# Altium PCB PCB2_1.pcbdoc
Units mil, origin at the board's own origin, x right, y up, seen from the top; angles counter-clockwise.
Board outline 3056.28 x 1755 mil, 2 copper layers (Top Layer, Bottom Layer); 62 components, 47 nets, 218 pads, 29 vias.
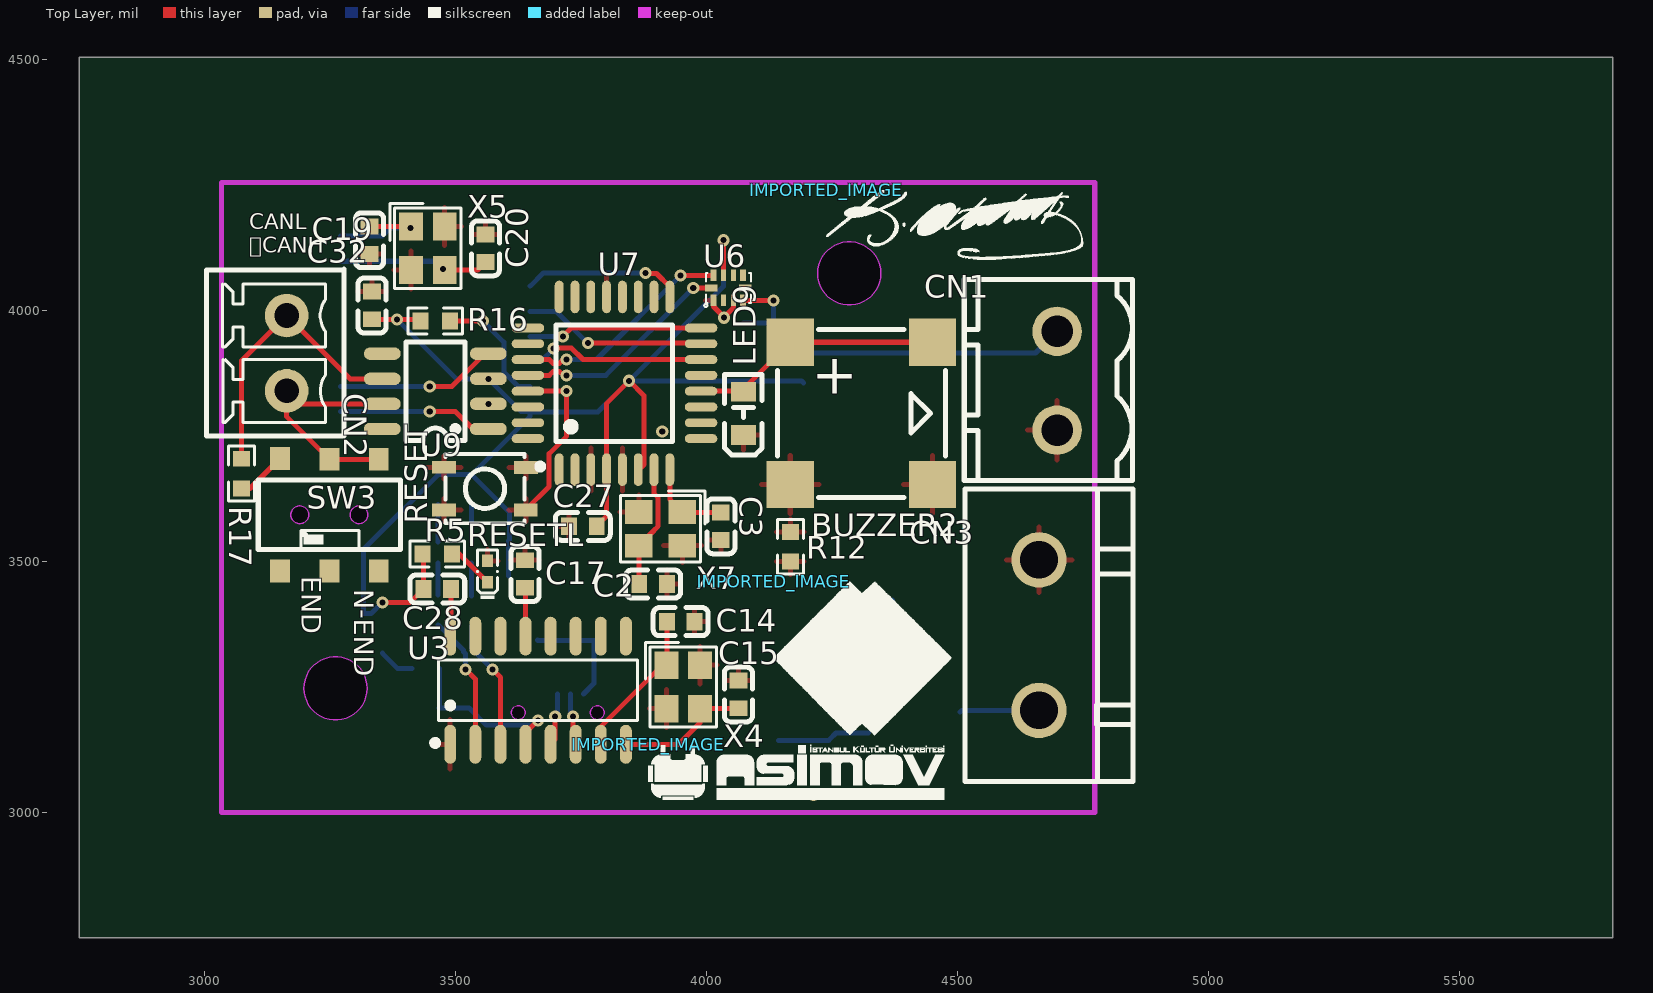
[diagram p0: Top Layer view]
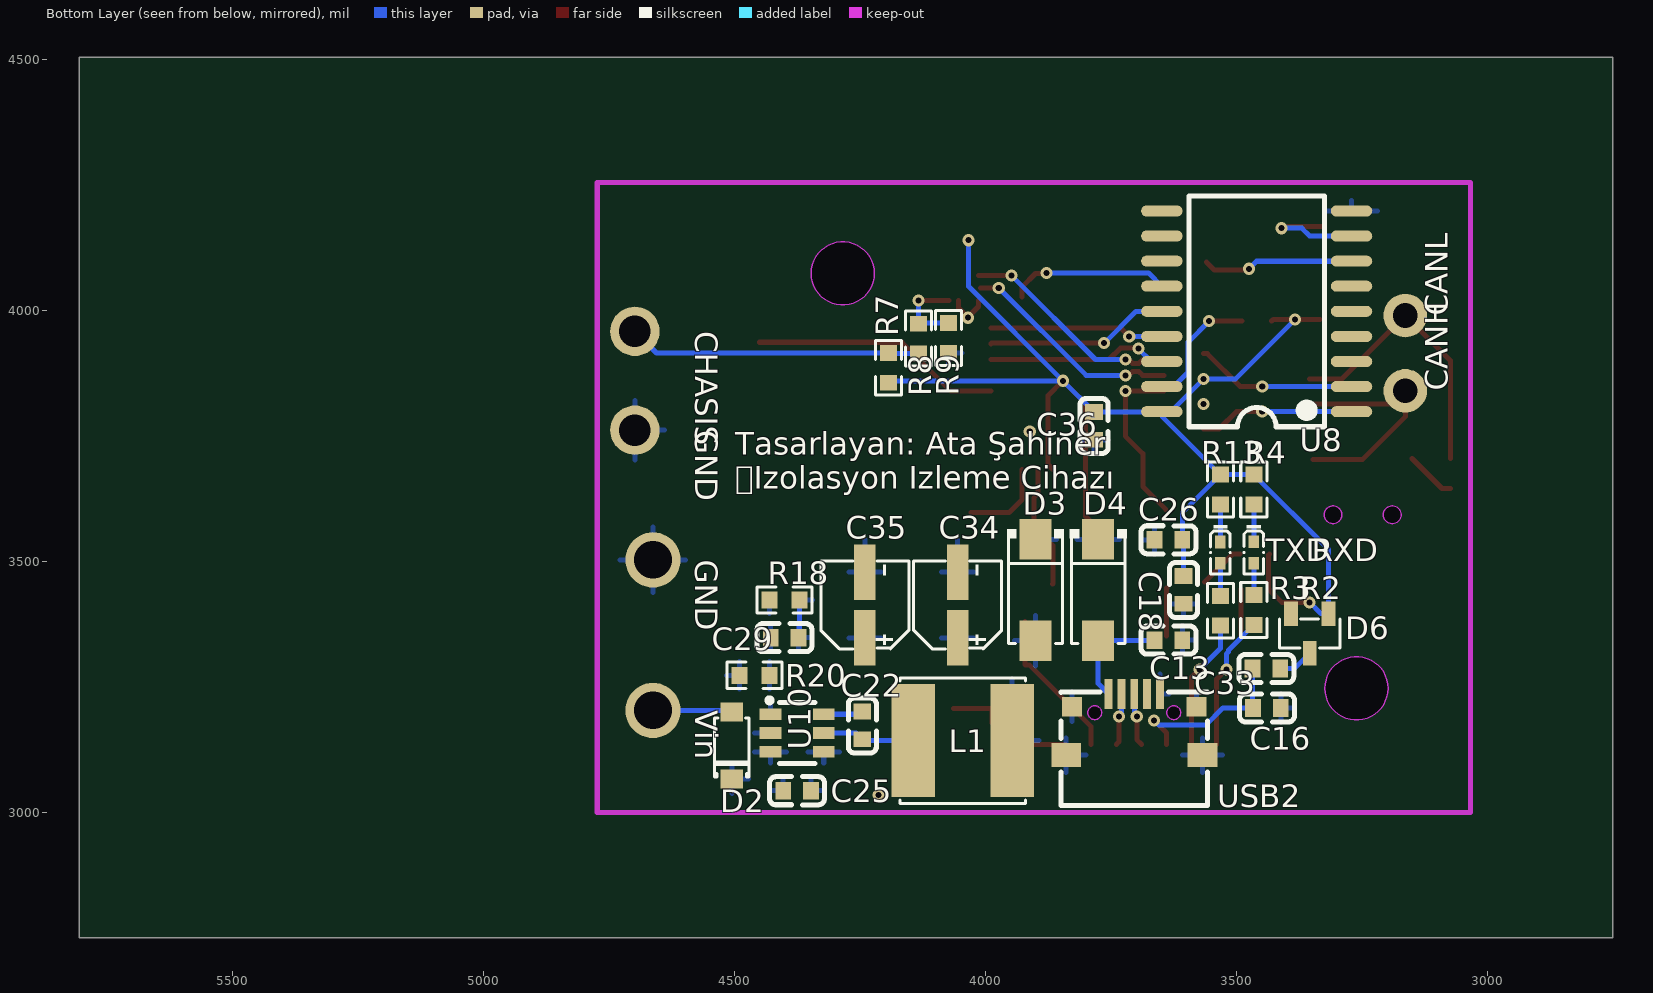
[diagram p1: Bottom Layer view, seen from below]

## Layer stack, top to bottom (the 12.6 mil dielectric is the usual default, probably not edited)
Top Layer: signal copper (thickness not stored)
Dielectric: dielectric 12.6, FR-4, Dk 4.8
Bottom Layer: signal copper (thickness not stored)

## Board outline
5806.28,2750 2750,2750 2750,4505 5806.28,4505
cut-out: 3323.98,3247.13 cw(c3260.99,3247.13) 3197.99,3247.13 cw(c3260.99,3247.13)
cut-out: 4347.6,4073.9 cw(c4284.61,4073.9) 4221.62,4073.9 cw(c4284.61,4073.9)

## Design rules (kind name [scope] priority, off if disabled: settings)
BoardOutlineClearance copperThickness1oz [All] p0: genericclearance=10 ignorepadtopadclearanceinfootprint=FALSE except(0: Arc-SplitContinuation Track-SplitContinuation SMDPad-SplitContinuation THPad-SplitContinuation Via-SplitContinuation Fill-SplitContinuation Poly-SplitContinuation Region-SplitContinuation Text-SplitContinuation; 6: Track-CutoutEdge SMDPad-CutoutEdge THPad-CutoutEdge Via-CutoutEdge Region-CutoutEdge; 11.8: Track-OutlineEdge SMDPad-OutlineEdge THPad-OutlineEdge Via-OutlineEdge Fill-OutlineEdge Region-OutlineEdge Poly-OutlineEdge Text-OutlineEdge Fill-CutoutEdge)
BoardOutlineClearance copperThickness2oz [All] p0: genericclearance=10 ignorepadtopadclearanceinfootprint=FALSE except(0: Arc-SplitContinuation Track-SplitContinuation SMDPad-SplitContinuation THPad-SplitContinuation Via-SplitContinuation Fill-SplitContinuation Poly-SplitContinuation Region-SplitContinuation Text-SplitContinuation; 6: Track-CutoutEdge SMDPad-CutoutEdge THPad-CutoutEdge Via-CutoutEdge Region-CutoutEdge; 11.8: Track-OutlineEdge SMDPad-OutlineEdge THPad-OutlineEdge Via-OutlineEdge Fill-OutlineEdge Region-OutlineEdge Poly-OutlineEdge Text-OutlineEdge Fill-CutoutEdge)
Clearance copperThickness1oz [(InNet('WARN') OR InNet('$1N38891') OR InNet('GND') OR InNet('XTAL2') OR InNet('$1N1971') OR InNet('XO') OR InNet('$1N3263') OR InNet('$1N3302') OR InNet('RESET') OR InNet('+5V') OR InNet('$1N37305') OR InNet('$1N27741') OR InNet('$1N42220') OR InNet('$1N28334') OR InNet('$1N30372') OR InNet('$1N32397') OR InNet('$1N42230') OR InNet('$1N42278') OR InNet('$1N45861') OR InNet('$1N5233') OR InNet('$1N28331') OR InNet('SDA') OR InNet('SCL') OR InNet('$1N3088') OR InNet('TXD') OR InNet('$1N3089') OR InNet('RXD') OR InNet('$1N44197') OR InNet('TXDC') OR InNet('RXDC') OR InNet('AIN0') OR InNet('$1N13750') OR InNet('$1N2618') OR InNet('INT') OR InNet('SCK') OR InNet('SO') OR InNet('SI') OR InNet('CS') OR InNet('RXCAN') OR InNet('XTAL1') OR InNet('XI') OR InNet('$1N37233') OR InNet('$1N2610') OR InNet('TXCAN') OR InNet('CANL') OR InNet('CANH') OR InNet('$1N53272'))] p1: gap=7 ignorepadtopadclearanceinfootprint=FALSE except(4: Track-Track; 6: Track-SMDPad SMDPad-SMDPad Track-THPad SMDPad-THPad THPad-THPad Track-Via SMDPad-Via THPad-Via Via-Via SMDPad-Fill THPad-Fill Via-Fill Fill-Fill Track-Region SMDPad-Region THPad-Region Via-Region Region-Region Track-Poly SMDPad-Poly THPad-Poly Via-Poly Fill-Poly Region-Poly Poly-Poly Track-Text SMDPad-Text THPad-Text Via-Text Fill-Text Region-Text Poly-Text Text-Text; 6.9: Track-Hole SMDPad-Hole THPad-Hole Via-Hole Fill-Hole Region-Hole Poly-Hole Text-Hole Sheet-Hole; 11.8: Track-Fill Fill-Region Track-Sheet SMDPad-Sheet THPad-Sheet Via-Sheet Fill-Sheet Region-Sheet Poly-Sheet Text-Sheet)
Clearance copperThickness2oz [All] p1: gap=7 ignorepadtopadclearanceinfootprint=FALSE except(6: Track-SMDPad SMDPad-SMDPad Track-THPad SMDPad-THPad THPad-THPad Track-Via SMDPad-Via THPad-Via Via-Via SMDPad-Fill THPad-Fill Via-Fill Fill-Fill Track-Region SMDPad-Region THPad-Region Via-Region Region-Region Track-Poly SMDPad-Poly THPad-Poly Via-Poly Fill-Poly Region-Poly Poly-Poly Track-Text SMDPad-Text THPad-Text Via-Text Fill-Text Region-Text Poly-Text Text-Text; 6.9: Track-Hole SMDPad-Hole THPad-Hole Via-Hole Fill-Hole Region-Hole Poly-Hole Text-Hole Sheet-Hole; 8: Track-Track; 11.8: Track-Fill Fill-Region Track-Sheet SMDPad-Sheet THPad-Sheet Via-Sheet Fill-Sheet Region-Sheet Poly-Sheet Text-Sheet)
DiffPairsRouting differentialPair [All] p1: maxuncoupledlength=10 minlimit=6 maxlimit=6 mostfreqgap=6 toplayer_minwidth=5 toplayer_prefwidth=10 toplayer_maxwidth=100 bottomlayer_minwidth=5 bottomlayer_prefwidth=10 bottomlayer_maxwidth=100
PasteMaskExpansion pasteMaskExpansion [All] p1: expansion=0
PlaneConnect innerPlane [All] p1: planeconnectstyle=Relief reliefexpansion=20 reliefentries=4 reliefconductorwidth=10 reliefairgap=10
PolygonConnect copperRegion [All] p1: connectstyle=Relief reliefentries=4 reliefconductorwidth=10 polygonreliefangle="90 Angle" airgapwidth=10
RoutingVias viaSize [All] p1: viastyle="Through Hole" holewidth=12.0078 minholewidth=11.811 maxholewidth=248.0314 width=24.0158 minwidth=19.685 maxwidth=393.7008
SolderMaskExpansion solderMaskExpansion [All] p1: useseparateexpansions=TRUE expansion=2 expansionbottom=2
Width copperThickness1oz [All] p1: maxlimit=100 minlimit=5 preferedwidth=10
Width copperThickness2oz [All] p1: maxlimit=100 minlimit=8 preferedwidth=10

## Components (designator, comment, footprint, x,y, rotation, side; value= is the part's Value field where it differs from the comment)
BUZZER2 "MLT-8530" BUZ-SMD_4P-L8.5-W8.5-P8.50-BR 4308.78,3795 r270 top
C2 "FCC1206N220J102DT" C0603 3893.78,3455 r0 top
C3 "FCC1206N220J102DT" C0603 4028.78,3570 r270 top
C13 "CC0603KRX7R9BB104" C0603 3635.63,3343.15 r0 bottom
C14 "FCC1206N220J102DT" C0603 3948.78,3380 r0 top
C15 "FCC1206N220J102DT" C0603 4063.78,3235 r90 top
C16 "CC0603KRX7R9BB104" C0603 3439.42,3208.05 r180 bottom
C17 "CC0603KRX7R9BB104" C0603 3638.78,3475 r270 top
C18 "CC0603KRX7R9BB104" C0603 3605.63,3443.15 r270 bottom
C19 "FCC1206N220J102DT" C0603 3328.78,4140 r270 top
C20 "FCC1206N220J102DT" C0603 3559.98,4123.93 r90 top
C22 "CC0603KRX7R9BB104" C0603 4245.63,3173.15 r90 bottom
C25 "CC0603KRX7R9BB104" C0603 4375.63,3043.15 r0 bottom
C26 "CC0603KRX7R9BB104" C0603 3635.63,3543.15 r180 bottom
C27 "CC0603KRX7R9BB104" C0603 3753.78,3570 r0 top
C28 "CC0603KRX7R9BB104" C0603 3463.78,3445 r180 top
C29 "CC0603KRX7R9BB104" C0603 4400.63,3348.15 r180 bottom
C32 "CC0603KRX7R9BB104" C0603 3333.78,4010 r270 top
C33 "CC0603KRX7R9BB104" C0603 3440.64,3286.44 r180 bottom
C34 "VT1H4R7M-CRC54" CAP-SMD_BD4.0-L4.3-W4.3-FD 4055.63,3413.15 r90 bottom
C35 "VT1H4R7M-CRC54" CAP-SMD_BD4.0-L4.3-W4.3-FD 4240.63,3413.15 r90 bottom
C36 "CC0603KRX7R9BB104" C0603 3783.78,3770 r90 bottom
CN1 "WJ2EDGV-5.08-2P_C8461" CONN-TH_WJ2EDGV-5.08-2P 4698.78,3860 r90 top
CN2 "WJ15EDGVC-3.81-2P_C8396" CONN-TH_WJ15EDGVC-3.81-2P 3163.78,3915 r270 top
CN3 "DB2EVC-7.62-2P-GN" CONN-TH_2P-P7.62_DB2EVC-7.62-2P 4662.72,3353.15 r270 top
D2 "BZT52C5V6_C173406" SOD-123_L2.8-W1.8-LS3.7-RD 4505.63,3133.15 r90 bottom
D3 "SS14_R1_00001" SMA_L4.4-W2.8-LS5.4-RD 3900.63,3443.15 r270 bottom
D4 "SS14_R1_00001" SMA_L4.4-W2.8-LS5.4-RD 3775.63,3443.15 r270 bottom
D6 "BZX84C5V1_R1_00001" SOT-23-3_L2.9-W1.3-P1.90-LS2.4-BR 3354.23,3356.5 r90 bottom
IMPORTED_IMAGE "IMPORTED_IMAGE" IMPORTED_IMAGE 4133.78,3460 r0 top
IMPORTED_IMAGE "IMPORTED_IMAGE" IMPORTED_IMAGE 4238.78,4240 r0 top
IMPORTED_IMAGE "IMPORTED_IMAGE" IMPORTED_IMAGE 3883.78,3135 r0 top
L1 "ASPI-0628-100M-T1" IND-SMD_L6.0-W6.0 4045.63,3143.15 r180 bottom
LED9 "YLED0805B" LED0805-RD 4073.78,3795 r90 top
R2 "1k" R0603 3465.61,3403.31 r270 bottom
R3 "1k" R0603 3532.21,3401.69 r270 bottom
R4 "1k" R0603 3465.59,3643.31 r90 bottom
R5 "10k" R0603 3463.78,3515 r180 top
R7 "1M" R0603 4193.78,3885.68 r90 bottom
R8 "1M" R0603 4133.45,3943.99 r90 bottom
R9 "82k" R0603 4073.78,3945 r270 bottom
R12 "220" R0603 4167.24,3529.26 r90 top
R13 "1k" R0603 3532.21,3643.31 r90 bottom
R16 "10k" R0603 3459.85,3978.93 r0 top
R17 "120" R0603 3073.78,3675 r270 top
R18 "576k" R0603 4400.63,3423.15 r180 bottom
R20 "113k" R0603 4460.63,3273.15 r0 bottom
RESET "PTS810SJS250SMTRLFS" SW-SMD_4P_PTS810SJM250SMTRLFS 3558.78,3645 r0 top
RESETL "LED_0402-R" LED0402-RD_YELLOW 3563.78,3480 r90 top
RXD "LED_0402-R" LED0402-RD_YELLOW 3465.59,3517.81 r270 bottom
SW3 "AYZ0202AGRLC" SW-SMD_AYZ0202AGRLC 3248.78,3592.99 r0 top
TXD "LED_0402-R" LED0402-RD_YELLOW 3532.21,3517.59 r270 bottom
U3 "CH340G" SOIC-16_L9.9-W3.9-P1.27-LS6.0-BL 3664.55,3243.4 r0 top
U6 "ADS1115IRUGR" X2QFN-10_L2.0-W1.5-P0.50-BL 4043.78,4045 r0 top
U7 "ATMEGA328P-AU_C14877" TQFP-32_L7.0-W7.0-P0.80-LS9.0-BL 3816.87,3854.99 r0 top
U8 "MCP2515T-I/SO" SOIC-18_L11.6-W7.5-P1.27-LS10.3-BL 3459.84,3998.39 r90 bottom
U9 "TJA1050DRG" SOP-8_L4.9-W3.9-P1.27-LS6.0-BL 3459.85,3838.93 r90 top
U10 "AP63200WU-7" SOT-23-6_L2.9-W1.6-P0.95-LS2.8-BR 4375.63,3158.15 r0 bottom
USB2 "MICRO QTZB5.5" MICRO-USB-SMD_MICRO-QTZB5.5 3703.78,3175 r180 bottom
X4 "TAXM8M4RDBCCT2T" CRYSTAL-SMD_4P-L3.2-W2.5-BL 3953.78,3250 r270 top
X5 "TAXM8M4RDBCCT2T" CRYSTAL-SMD_4P-L3.2-W2.5-BL 3444.98,4123.93 r270 top
X7 "TAXM8M4RDBCCT2T" CRYSTAL-SMD_4P-L3.2-W2.5-BL 3908.78,3565 r180 top

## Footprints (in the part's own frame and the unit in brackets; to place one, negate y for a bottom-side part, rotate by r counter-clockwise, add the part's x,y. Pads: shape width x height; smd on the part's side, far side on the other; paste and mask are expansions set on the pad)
BUZ-SMD_4P-L8.5-W8.5-P8.50-BR [mil]
  rect 94.49x94.49 smd: 1(-141.72,-141.73) 2(141.72,-141.73) 3(141.72,141.72) 4(-141.72,141.73)
  silkscreen extent -167,-167 167,167
C0603 [mm]
  rect 0.8x0.9 smd: 1(-0.7,0) 2(0.7,0)
  silkscreen extent -1.39,-0.71 1.39,0.71
CAP-SMD_BD4.0-L4.3-W4.3-FD [mm]
  rect 2.8x1.1 smd: 1(-1.661,0) 2(1.661,0)
  silkscreen extent -2.22,-2.23 2.24,2.23
CONN-TH_2P-P7.62_DB2EVC-7.62-2P [mm]
  round 2.8 hole 1.9: 1(-3.81,0) 2(3.81,0)
  silkscreen extent -7.4,-3.75 7.4,4.75
CONN-TH_WJ2EDGV-5.08-2P [mm]
  round 2.5 hole 1.6: 1(-2.499,0) 2(2.499,0)
  silkscreen extent -5.04,-3.81 5.12,4.7
CONN-TH_WJ15EDGVC-3.81-2P [mm]
  round 2.2 hole 1.25: 1(-1.905,0) 2(1.905,0)
  silkscreen extent -4.26,-4.06 4.2,2.9
CRYSTAL-SMD_4P-L3.2-W2.5-BL [mm]
  rect 1.4x1.2 smd: 1(-1.1,-0.85) 2(1.1,-0.85) 3(1.1,0.85) 4(-1.1,0.85)
  silkscreen extent -2.26,-1.91 2.03,1.68
IMPORTED_IMAGE [mil]
  silkscreen extent 0,-307 354,0
IND-SMD_L6.0-W6.0 [mm]
  rect 2.2x5.72 smd: 1(-2.5,0) 2(2.5,0)
  silkscreen extent -3.18,-3.18 3.18,3.18
LED0402-RD_YELLOW [mm]
  rect 0.636x0.54 smd: 1(-0.538,0) 2(0.538,0)
  silkscreen extent -1.39,-0.54 1.09,0.54
LED0805-RD [mm]
  rect 1x1.25 smd: 1(-1.1,0) 2(1.1,0)
  silkscreen extent -2.1,-0.95 1.98,0.96
MICRO-USB-SMD_MICRO-QTZB5.5 [mm]
  rect 0.4x1.524 smd: 1(-1.3,1.55) 2(-0.65,1.55) 3(0,1.55) 4(0.65,1.55) 5(1.3,1.55)
  rect 1.5x1.22 smd: 6(-3.45,-1.55) 7(3.45,-1.55)
  rect 1x1 smd: 6(-3.15,0.9) 7(3.15,0.9)
  Board Outline Layer circle w0.005: c-2,0.6 r0.35
  Board Outline Layer circle w0.005: c2,0.6 r0.35
  Board Outline Layer region: -2.35,0.6 -2.315,0.448 -2.218,0.326 -2.078,0.259 -1.922,0.259 -1.782,0.326 -1.685,0.448 -1.65,0.6 -1.65,0.6 -1.685,0.752 -1.782,0.874 -1.922,0.941 -2.078,0.941 -2.218,0.874 -2.315,0.752 -2.35,0.6
  Board Outline Layer region: 1.65,0.6 1.685,0.448 1.782,0.326 1.922,0.259 2.078,0.259 2.218,0.326 2.315,0.448 2.35,0.6 2.35,0.6 2.315,0.752 2.218,0.874 2.078,0.941 1.922,0.941 1.782,0.874 1.685,0.752 1.65,0.6
  Multi-Layer board cut-out: -2.35,0.6 -2.315,0.448 -2.218,0.326 -2.078,0.259 -1.922,0.259 -1.782,0.326 -1.685,0.448 -1.65,0.6 -1.65,0.6 -1.685,0.752 -1.782,0.874 -1.922,0.941 -2.078,0.941 -2.218,0.874 -2.315,0.752 -2.35,0.6
  Multi-Layer board cut-out: 1.65,0.6 1.685,0.448 1.782,0.326 1.922,0.259 2.078,0.259 2.218,0.326 2.315,0.448 2.35,0.6 2.35,0.6 2.315,0.752 2.218,0.874 2.078,0.941 1.922,0.941 1.782,0.874 1.685,0.752 1.65,0.6
  silkscreen extent -3.7,-4.1 3.7,1.65
R0603 [mil]
  rect 31.75x34.02 smd: 1(-29.66,0) 2(29.66,0)
  silkscreen extent -55,-26 55,26
SMA_L4.4-W2.8-LS5.4-RD [mil]
  rect 80.57x63.78 smd: 1(-101,0) 2(101,0)
  silkscreen extent -121,-57 106,57
SOD-123_L2.8-W1.8-LS3.7-RD [mm]
  rect 0.95x1.15 smd: 1(-1.692,0) 2(1.692,0)
  silkscreen extent -1.58,-0.87 1.41,0.87
SOIC-16_L9.9-W3.9-P1.27-LS6.0-BL [mil]
  oval 23.7x77.6 smd: 1(-175,-107.7) 2(-125,-107.7) 3(-75,-107.7) 4(-25,-107.7) 5(25,-107.7) 6(75,-107.7) 7(125,-107.7) 8(175,-107.7) 9(175,107.7) 10(125,107.7) 11(75,107.7) 12(25,107.7) 13(-25,107.7) 14(-75,107.7) 15(-125,107.7) 16(-175,107.7)
  silkscreen extent -211,-111 198,60
SOIC-18_L11.6-W7.5-P1.27-LS10.3-BL [mm]
  oval 0.56x2.1 smd: 1(-5.08,-4.8) 2(-3.81,-4.8) 3(-2.54,-4.8) 4(-1.27,-4.8) 5(0,-4.8) 6(1.27,-4.8) 7(2.54,-4.8) 8(3.81,-4.8) 9(5.08,-4.8) 10(5.08,4.8) 11(3.81,4.8) 12(2.54,4.8) 13(1.27,4.8) 14(0,4.8) 15(-1.27,4.8) 16(-2.54,4.8) 17(-3.81,4.8) 18(-5.08,4.8)
  silkscreen extent -5.84,-3.43 5.84,3.43
SOP-8_L4.9-W3.9-P1.27-LS6.0-BL [mm]
  oval 0.63x1.865 smd: 1(-1.905,-2.682) 2(-0.635,-2.682) 3(0.635,-2.682) 4(1.905,-2.682) 5(1.905,2.682) 6(0.635,2.682) 7(-0.635,2.682) 8(-1.905,2.682)
  silkscreen extent -2.5,-1.5 2.5,1.48
SOT-23-3_L2.9-W1.3-P1.90-LS2.4-BR [mm]
  rect 1.25x0.7 smd: 1(1,-0.95) 2(1,0.95) 3(-1,0)
  silkscreen extent -0.73,-1.53 0.73,1.53
SOT-23-6_L2.9-W1.6-P0.95-LS2.8-BR [mm]
  rect 1.1x0.6 smd: 1(1.35,-0.95) 2(1.35,0) 3(1.35,0.95) 4(-1.35,0.95) 5(-1.35,0) 6(-1.35,-0.95)
  silkscreen extent -0.9,-1.78 1.52,1.55
SW-SMD_4P_PTS810SJM250SMTRLFS [mm]
  rect 1.2x0.65 smd: 1(-2.078,1.083) 2(2.078,1.076) 3(-2.077,-1.083) 4(2.071,-1.075)
  silkscreen extent -2,-1.75 2,1.75
SW-SMD_AYZ0202AGRLC [mm]
  rect 1x1.15 smd: 1(-2.5,2.845) 2(0,2.805) 3(2.5,2.805) 4(-2.5,-2.845) 5(0,-2.845) 6(2.5,-2.845)
  Board Outline Layer circle w0.005: c-1.5,0 r0.45
  Board Outline Layer circle w0.005: c1.5,0 r0.45
  Board Outline Layer region: -1.05,0 -1.095,-0.195 -1.219,-0.352 -1.4,-0.439 -1.6,-0.439 -1.781,-0.352 -1.905,-0.195 -1.95,0 -1.95,0 -1.905,0.195 -1.781,0.352 -1.6,0.439 -1.4,0.439 -1.219,0.352 -1.095,0.195 -1.05,0
  Board Outline Layer region: 1.95,0 1.905,-0.195 1.781,-0.352 1.6,-0.439 1.4,-0.439 1.219,-0.352 1.095,-0.195 1.05,0 1.05,0 1.095,0.195 1.219,0.352 1.4,0.439 1.6,0.439 1.781,0.352 1.905,0.195 1.95,0
  Multi-Layer board cut-out: -1.05,0 -1.095,-0.195 -1.219,-0.352 -1.4,-0.439 -1.6,-0.439 -1.781,-0.352 -1.905,-0.195 -1.95,0 -1.95,0 -1.905,0.195 -1.781,0.352 -1.6,0.439 -1.4,0.439 -1.219,0.352 -1.095,0.195 -1.05,0
  Multi-Layer board cut-out: 1.95,0 1.905,-0.195 1.781,-0.352 1.6,-0.439 1.4,-0.439 1.219,-0.352 1.095,-0.195 1.05,0 1.05,0 1.095,0.195 1.219,0.352 1.4,0.439 1.6,0.439 1.781,0.352 1.905,0.195 1.95,0
  silkscreen extent -3.6,-1.75 3.6,1.75
TQFP-32_L7.0-W7.0-P0.80-LS9.0-BL [mm]
  oval 0.45x1.65 smd: 1(-2.8,-4.369) 2(-2,-4.369) 3(-1.2,-4.369) 4(-0.4,-4.369) 5(0.4,-4.369) 6(1.2,-4.369) 7(2,-4.369) 8(2.8,-4.369) 17(2.8,4.369) 18(2,4.369) 19(1.2,4.369) 20(0.4,4.369) 21(-0.4,4.369) 22(-1.2,4.369) 23(-2,4.369) 24(-2.8,4.369)
  oval 1.65x0.45 smd: 9(4.381,-2.8) 10(4.381,-2) 11(4.381,-1.2) 12(4.381,-0.4) 13(4.381,0.4) 14(4.381,1.2) 15(4.381,2) 16(4.381,2.8) 25(-4.381,2.8) 26(-4.381,2) 27(-4.381,1.2) 28(-4.381,0.4) 29(-4.381,-0.4) 30(-4.381,-1.2) 31(-4.381,-2) 32(-4.381,-2.8)
  silkscreen extent -3.91,-4.36 2.94,2.95
X2QFN-10_L2.0-W1.5-P0.50-BL [mm]
  rect 0.3x0.58 smd: 1(-0.75,-0.635) 4(0.75,-0.635) 6(0.75,0.635) 9(-0.75,0.635)
  rect 0.25x0.58 smd: 2(-0.25,-0.635) 3(0.25,-0.635) 7(0.25,0.635) 8(-0.25,0.635)
  rect 0.63x0.35 smd: 5(0.86,0) 10(-0.86,0)
  silkscreen extent -1.22,-0.97 1.14,0.76

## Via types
v1: diameter 24.02, hole 12.01, Top Layer to Bottom Layer, 29 vias

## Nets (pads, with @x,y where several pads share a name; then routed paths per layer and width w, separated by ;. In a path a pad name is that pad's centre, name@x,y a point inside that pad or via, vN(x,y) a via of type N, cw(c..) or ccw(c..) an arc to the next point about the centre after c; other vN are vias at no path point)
$1N1971: C13.2 D4.2 USB2.1 | length 227.5
  Bottom Layer w10: C13.2 3664.19,3342.15 D4.2 3775.63,3256.69 USB2.1
$1N2610: U3.5 USB2.3 | length 106.2
  Top Layer w10: U3.5 3698.78,3144.93 v1(3698.78,3191.03)
  Bottom Layer w10: v1(3698.78,3191.03) 3703.78,3196.03 USB2.3
$1N2618: U3.6 USB2.2 | length 104.5
  Top Layer w10: v1(3734.37,3191.03) 3734.37,3140.87 U3.6
  Bottom Layer w10: USB2.2 3729.37,3196.03 v1(3734.37,3191.03)
$1N3088: R13.1 TXD.1 | length 74.9
  Bottom Layer w10: TXD.1 R13.1
$1N3089: R4.1 RXD.1 | length 74.6
  Bottom Layer w10: RXD.1 R4.1
$1N3263: C16.1 C33.1 U3.4 | length 352.8
  Top Layer w10: U3.4 3639.55,3158.5 v1(3664.55,3183.5)
  Bottom Layer w10: C33.1 3468.2,3209.27 C16.1 3527.25,3208.05 3561.43,3173.86 3654.91,3173.86 v1(3664.55,3183.5)
$1N3302: C17.2 U3.13 | length 96.7
  Top Layer w10: C17.2 3639.55,3446.67 U3.13
$1N5233: CN1.2 R7.2 R8.1 | length 583.6
  Bottom Layer w10: R8.1 4192.77,3914.33 R7.2 4655.72,3915.34 CN1.2
$1N13750: R16.2 U8.17 | length 248.3
  Top Layer w10: R16.2 v1(3554.51,3978.93)
  Bottom Layer w10: v1(3554.51,3978.93) 3596.5,3936.94 3596.5,3877.28 3625.39,3848.39 U8.17
$1N27741: C22.2 U10.6 | length 79
  Bottom Layer w10: C22.2 4250.79,3195.55 U10.6
$1N28331: CN3.2 D2.2 | length 158.5
  Bottom Layer w10: D2.2 4509,3203.15 CN3.2
$1N28334: C25.2 D2.1 U10.2 U10.3
$1N30372: C26.1 D3.1 D4.1
$1N32397: C28.1 U3.16 | length 94.6
  Top Layer w10: U3.16 3491.34,3352.89 C28.1
$1N37233: C19.1 U8.8 X5.1 | length 230.6
  Top Layer w10: C19.1 3329.1,4167.24 X5.1 X5.1@3409.97,4165.7
  Bottom Layer w10: U8.8 3354.43,4148.39 3369.97,4163.93 v1(3409.97,4163.93)
$1N37305: C20.1 U8.7 X5.3 | length 303
  Top Layer w10: v1(3475.13,4083.14) 3475.71,4083.14 3478.23,4080.62 X5.3 3544.23,4080.62 C20.1
  Bottom Layer w10: U8.7 3271.11,4098.14 3460.13,4098.14 v1(3475.13,4083.14)
$1N38891: BUZZER2.2 BUZZER2.3 LED9.1 R12.2
$1N42220: C22.1 L1.1 U10.5 | length 184.6
  Bottom Layer w10: L1.1 4243.19,3143.15 C22.1 4258.19,3158.15 U10.5
$1N42230: C29.2 C34.1 C35.1 D3.2 L1.2 R18.2 | length 75.9
  Bottom Layer w10: R18.2 4370.97,3350.25 C29.2
$1N42278: C29.1 R18.1 R20.1 U10.1
$1N44197: R5.1 RESETL.1 | length 93.6
  Top Layer w10: R5.1 3507.59,3515 RESETL.1
$1N45861: C33.2 D6.3 | length 71.6
  Bottom Layer w10: D6.3 3384.92,3286.44 C33.2
$1N53272: R17.2 SW3.1 | length 101.3
  Top Layer w10: R17.2 3090.7,3645.34 SW3.1
+5V: C18.1 C26.2 C27.2 C28.2 C32.2 C36.2 D6.1 R4.2 R5.2 R7.1 R13.2 R16.1 U6.8 U7.4 U7.6 U8.18 U9.3 | length 2976.5
  Top Layer w10: C32.2 v1(3383.26,3982.44) 3426.68,3982.44 R16.1 ; v1(3354.23,3418.51) 3409.73,3418.51 C28.2 3436.22,3512.9 R5.2 ; C27.2 3801.12,3589.78 U7.4 ; U7.4 3801.14,3815 v1(3846.14,3860) 3875.77,3830.37 3875.77,3692.99 3865.77,3682.99 U7.6 ; v1(4033.78,4140) 4033.94,4139.84 U6.8
  Bottom Layer w10: v1(3354.23,3418.51) 3331.59,3395.87 D6.1 3316.83,3524.21 R4.2 R13.2 ; v1(3383.26,3982.44) 3501.77,3863.93 v1(3565.46,3863.93) 3631,3798.39 U8.18 ; C18.1 3605.63,3540.71 C26.2 3608.07,3597.11 R13.2 ; C36.2 3649.65,3797.56 U8.18 ; C36.2 v1(3846.14,3860) ; v1(4033.78,4140) 4033.78,4047.64 v1(3846.14,3860) ; R7.1 4189.8,3860 v1(3846.14,3860) ; R13.2 3648.82,3789.58 U8.18
AIN0: R8.2 R9.1 U6.4 | length 167
  Top Layer w10: U6.4 v1(4133.78,4020)
  Bottom Layer w10: R9.1 4132.43,3974.66 R8.2 4133.45,4019.67 v1(4133.78,4020)
CANH: CN2.2 SW3.2 SW3.3 U9.7 | length 471.5
  Top Layer w10: SW3.3 SW3.2 3163.78,3788.41 CN2.2 3189.85,3813.93 U9.7
CANL: CN2.1 R17.1 U9.6 | length 565.3
  Top Layer w10: R17.1 3073.78,3900 CN2.1 3289.85,3863.93 U9.6
CS: U7.14 U8.16 | length 361.2
  Top Layer w10: v1(3695.78,3924) 3697.01,3925.23 3730.98,3925.23 3753.97,3902.23 U7.14
  Bottom Layer w10: U8.16 3670.17,3898.39 v1(3695.78,3924)
GND: C2.2 C3.2 C13.1 C14.2 C15.2 C16.2 C18.2 C19.2 C20.2 C25.1 C27.1 C32.1 C34.2 C35.2 C36.1 CN1.1 CN3.1 R9.2 R12.1 R20.2 RESET.1 RESET.2 U3.1 U6.1 U6.3 U7.3 U7.5 U7.21 U8.9 U9.2 U10.4 USB2.5 USB2.6 USB2.7 X4.2 X4.4 X5.2 X5.4 X7.2 X7.4 | length 84.5
  Top Layer w10: U6.1 4014.25,4007.82 4035.05,3987.02 v1@4035.05,3986.27 ; v1(4035.05,3985.59) v1@4035.05,3986.27 ; U6.3 4053.62,4004.84 v1@4035.05,3986.27
  other v1: 4213.78,3034.83 3912.04,3759.35 3565.46,3813.93
INT: U7.32
RESET: C17.1 RESET.3 RESET.4 RESETL.2 U7.29 | length 347.2
  Top Layer w10: RESET.4 3686.79,3649.17 3686.79,3714.83 3721.46,3749.5 v1(3721.46,3839.25) U7.29
RXCAN: U8.2 U9.4 | length 321.7
  Top Layer w10: v1(3448.78,3848.93) 3493.08,3848.93 3558.08,3913.93 U9.4
  Bottom Layer w10: U8.2 3448.24,3848.39 v1(3448.78,3848.93)
RXD: R2.1 RXD.2 | length 63.6
  Bottom Layer w10: R2.1 RXD.2
RXDC: R3.2 U3.3 | length 260.1
  Top Layer w10: v1(3573.78,3285) 3589.55,3269.23 U3.3
  Bottom Layer w10: R3.2 3532.21,3326.57 v1(3573.78,3285)
SCK: U7.17 U8.13 | length 321
  Top Layer w10: v1(3878.78,4075) 3879.95,4073.83 3900.46,4073.83 3927.11,4047.18 U7.17
  Bottom Layer w10: U8.13 3675.43,4075 v1(3878.78,4075)
SCL: U6.10 U7.28 | length 444.1
  Top Layer w10: U7.28 3686.85,3870.74 3694.6,3878.49 3707.09,3878.49 3714.83,3870.75 v1(3721.46,3870.75) ; v1(3973.78,4045) U6.10
  Bottom Layer w10: v1(3721.46,3870.75) 3799.53,3870.75 v1(3973.78,4045)
SDA: U6.9 U7.27 | length 445.8
  Top Layer w10: U7.27 3686.85,3902.23 3694.6,3894.49 3707.08,3894.49 3714.83,3902.23 v1(3721.46,3902.23) ; v1(3948.78,4070) U6.9
  Bottom Layer w10: v1(3721.46,3902.23) 3781.02,3902.23 v1(3948.78,4070)
SI: U7.15 U8.14 | length 367.3
  Top Layer w10: v1(3763.78,3935) 3988.1,3935 U7.15
  Bottom Layer w10: U8.14 3700.39,3998.39 v1(3763.78,3935)
SO: U7.16 U8.15 | length 347.5
  Top Layer w10: v1(3713.82,3948.39) 3730.66,3965.23 U7.16
  Bottom Layer w10: U8.15 v1(3713.82,3948.39)
TXCAN: U8.1 U9.1 | length 309.3
  Top Layer w10: v1(3448.78,3798.93) 3499.85,3798.93 3534.85,3763.93 U9.1
  Bottom Layer w10: U8.1 3448.24,3798.39 v1(3448.78,3798.93)
TXD: R3.1 TXD.2 | length 65
  Bottom Layer w10: R3.1 TXD.2
TXDC: R2.2 U3.2 | length 268.6
  Top Layer w10: v1(3520.4,3285) 3539.55,3265.85 U3.2
  Bottom Layer w10: R2.2 3516.21,3323.05 3516.21,3319.94 3520.4,3315.75 v1(3520.4,3285)
WARN: BUZZER2.1 BUZZER2.4 LED9.2 U7.12 | length 501.5
  Top Layer w10: U7.12 4069.57,3839.24 BUZZER2.1 BUZZER2.4
XI: C14.1 U3.7 X4.1 | length 303.6
  Top Layer w10: U3.7 3789.55,3170.63 3912.23,3293.31 X4.1 3921.22,3294.22 C14.1
XO: C15.1 U3.8 X4.3 | length 270.5
  Top Layer w10: U3.8 3944.48,3135.7 3987.25,3178.47 X4.3 4063.03,3206.69 C15.1
XTAL1: C2.1 U7.7 X7.3 | length 247.7
  Top Layer w10: C2.1 3865.47,3455.75 X7.3 3895.61,3561.68 3895.61,3561.89 3904.01,3570.29 3904.01,3626.64 3895.61,3635.04 U7.7
XTAL2: C3.1 U7.8 X7.1 | length 171.9
  Top Layer w10: U7.8 3927.11,3623.45 X7.1 3953,3597.56 C3.1
pads on no net: D6.2 SW3.4 SW3.5 SW3.6 U3.9 U3.10 U3.11 U3.12 U3.14 U3.15 U6.2 U6.5 U6.6 U6.7 U7.1 U7.2 U7.9 U7.10 U7.11 U7.13 U7.18 U7.19 U7.20 U7.22 U7.23 U7.24 U7.25 U7.26 U7.30 U7.31 U8.3 U8.4 U8.5 U8.6 U8.10 U8.11 U8.12 U9.5 U9.8 USB2.4

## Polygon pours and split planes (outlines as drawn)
$1N38891 on Top Layer (solid, remove dead copper, pour order 0): 4036.38,3775.31 4503.78,3775.31 4503.78,3530 4036.38,3530
$1N42278 on Bottom Layer (solid, remove dead copper, pour order 10): 4400.63,3449.16 4453.69,3449.16 4453.69,3176.55 4400.63,3176.55
GND on Top Layer (solid, remove dead copper, pour order 4): 3043.78,4245 4763.78,4245 4763.78,3015 3043.78,3015
$1N30372 on Bottom Layer (solid, remove dead copper, pour order 12): 3643.17,3591.87 3936.48,3591.87 3936.48,3495.31 3643.17,3495.31
GND on Bottom Layer (solid, remove dead copper, pour order 14): 3043.78,4240 4763.78,4240 4763.78,3015 3043.78,3015
$1N42230 on Bottom Layer (solid, remove dead copper, pour order 6): 4400.63,3449.16 4400.63,3301.49 4389.6,3290.45 4007.01,3290.45 4007.01,3018.1 3861.88,3018.1 3858.78,3015 3858.78,3410.5 4324.28,3410.5 4328.78,3415 4328.78,3445 4323.78,3450 4399.79,3450
RESET on Top Layer (solid, remove dead copper, pour order 2): 3439.58,3643.31 3439.58,3564.4 3493.19,3564.4 3544.15,3513.44 3544.15,3491.66 3549.78,3486.03 3676.75,3486.03 3676.75,3643.18 3676.62,3643.31
$1N28334 on Bottom Layer (solid, remove dead copper, pour order 8): 4401.09,3166.61 4539.73,3166.61 4539.73,3020 4375.63,3020 4375.63,3141.15

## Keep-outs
Board Outline Layer:
  circle w1: c3260.99,3247.13 r62.99
  region: 3323.98,3247.13 cw(c3260.99,3247.13) 3197.99,3247.13 cw(c3260.99,3247.13)
  circle w1: c4284.61,4073.9 r62.99
  region: 4347.6,4073.9 cw(c4284.61,4073.9) 4221.62,4073.9 cw(c4284.61,4073.9)
  lines w10: 3033.78,3000 4773.78,3000 4773.78,4255 3033.78,4255 3033.78,3000

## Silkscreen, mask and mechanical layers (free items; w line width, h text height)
Top Silkscreen Layer:
  text "CANL /  CANH" at 3088.78,4115 h31.5
  text "END" at 3193.78,3470 h39.37 r270
  text "N-END" at 3298.78,3445 h39.37 r270
Bottom Silkscreen Layer:
  text "CANL" at 3078.78,3990 h45 r270
  text "CHASIS" at 4578.11,3958.39 h45 r90
  text "CANH" at 3078.78,3840 h45 r270
  text "GND" at 4578.11,3761.61 h45 r90
  text "Tasarlayan: Ata Şahiner /  Izolasyon Izleme Cihazı" at 4498.78,3645 h45
  text "GND" at 4578.11,3503.15 h45 r90
  text "Vin" at 4578.1,3203.15 h45 r90
Mechanical Layer:
  circle w1: c3260.99,3247.13 r62.99
  circle w1: c4284.61,4073.9 r62.99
